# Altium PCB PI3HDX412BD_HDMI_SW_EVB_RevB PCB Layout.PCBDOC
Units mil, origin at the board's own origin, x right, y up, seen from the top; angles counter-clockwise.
Board outline 3710 x 2823 mil, 4 copper layers (Top Layer, MidLayer2, MidLayer1, Bottom Layer); 75 components, 78 nets, 342 pads, 126 vias.
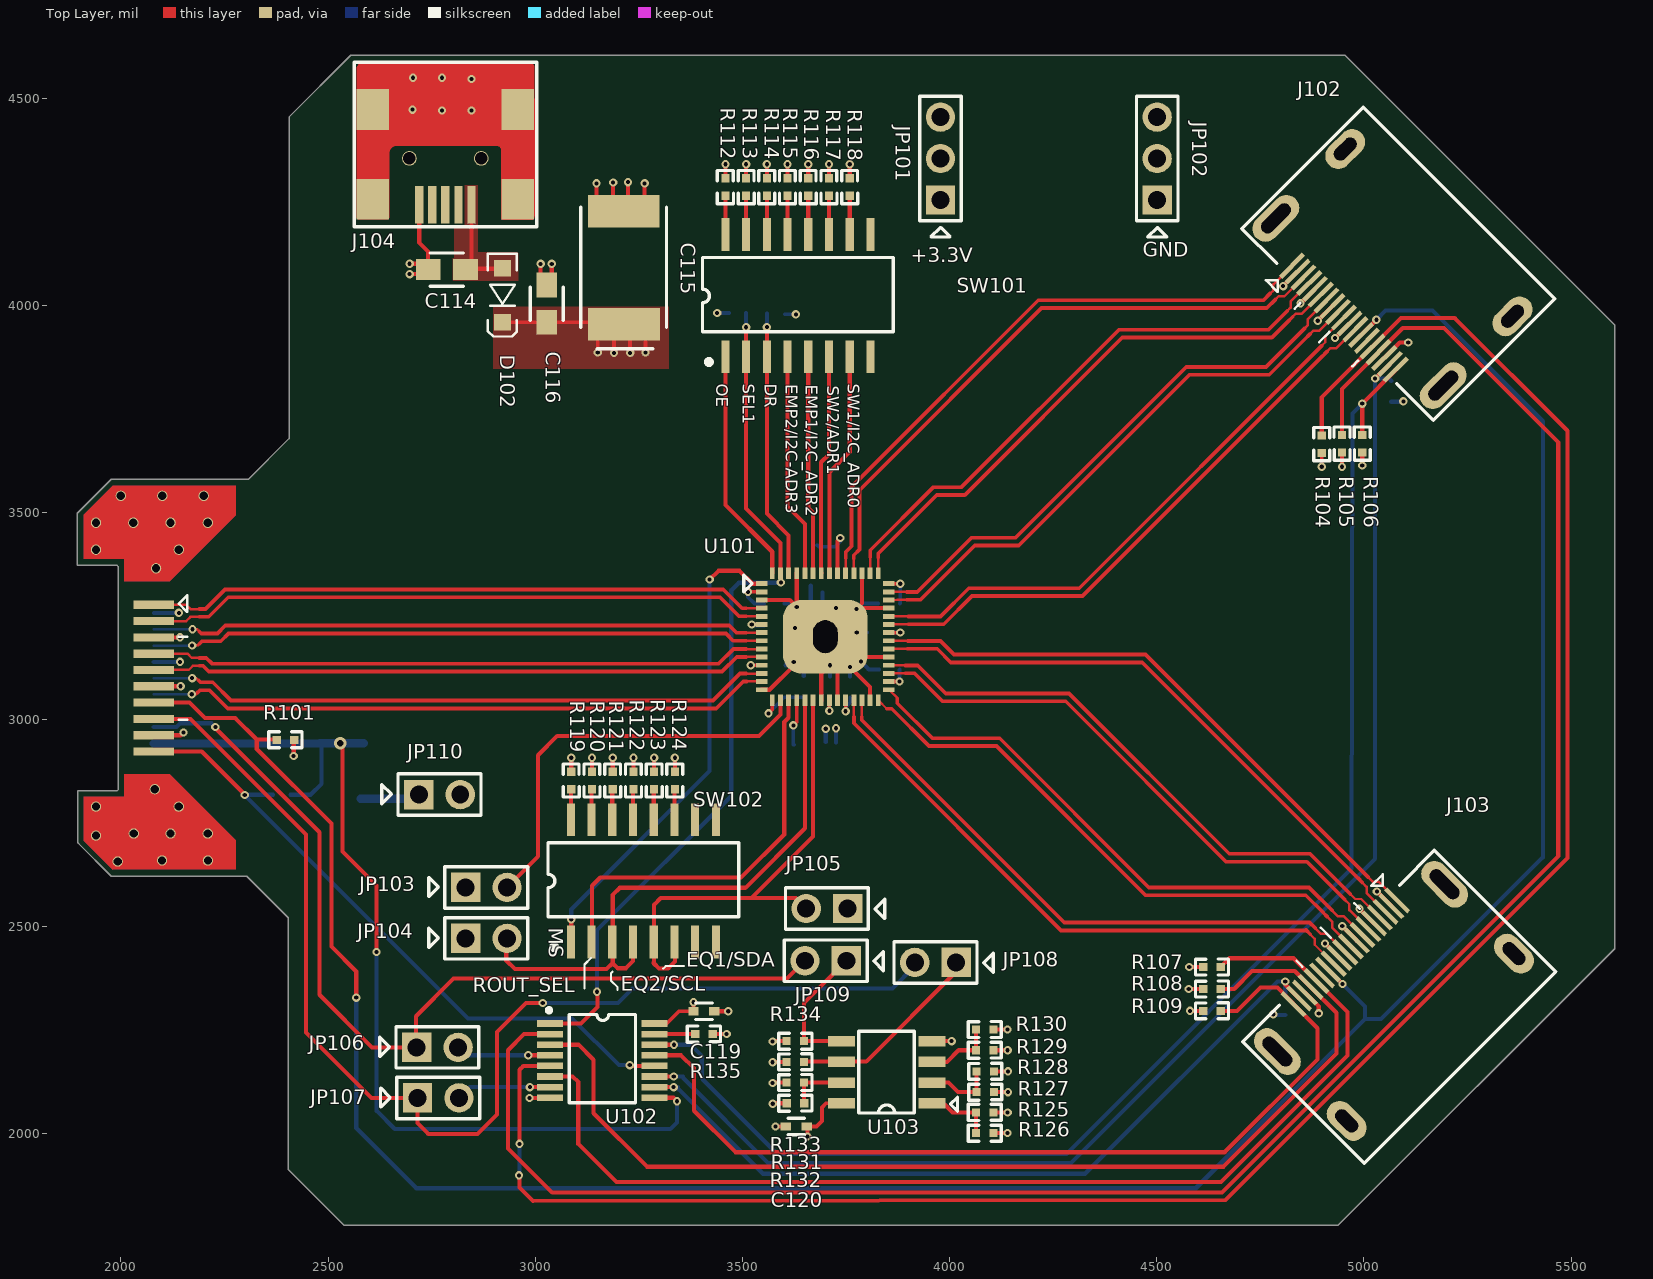
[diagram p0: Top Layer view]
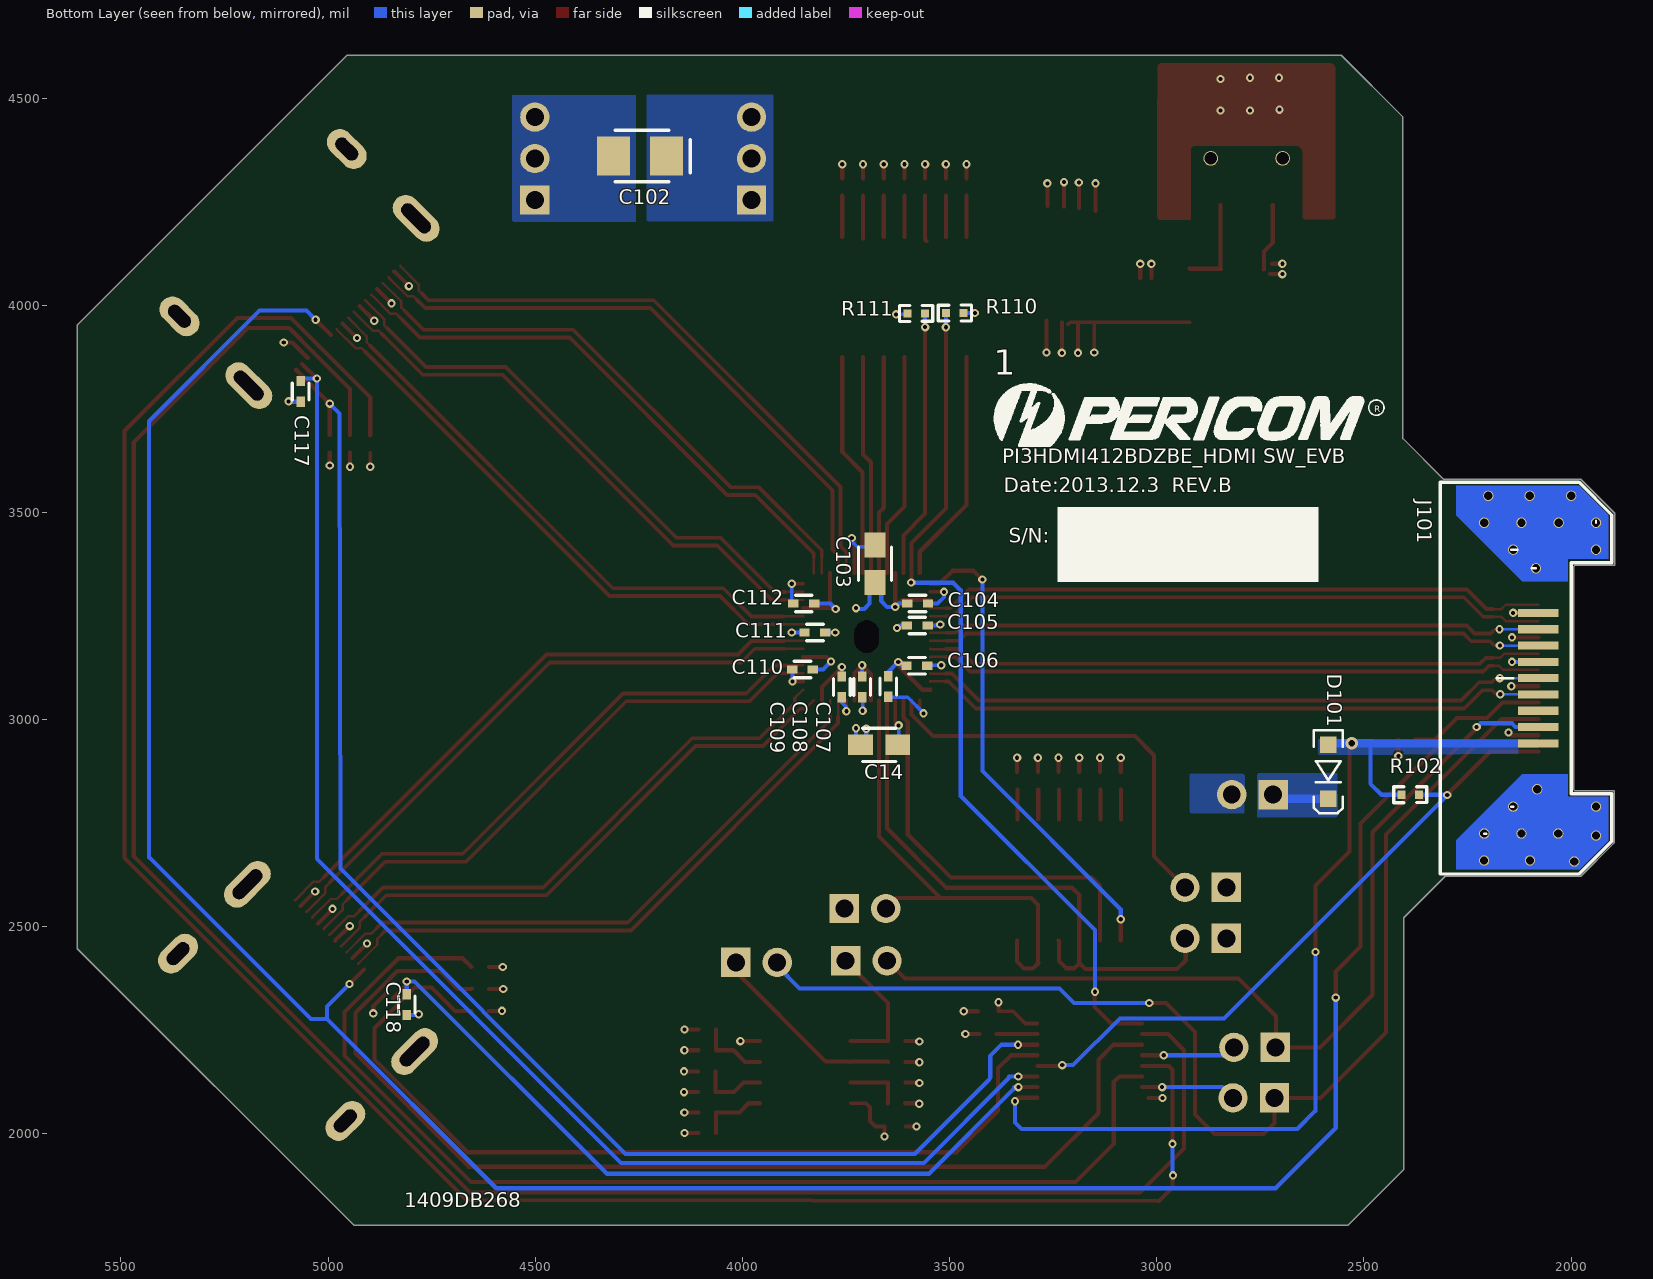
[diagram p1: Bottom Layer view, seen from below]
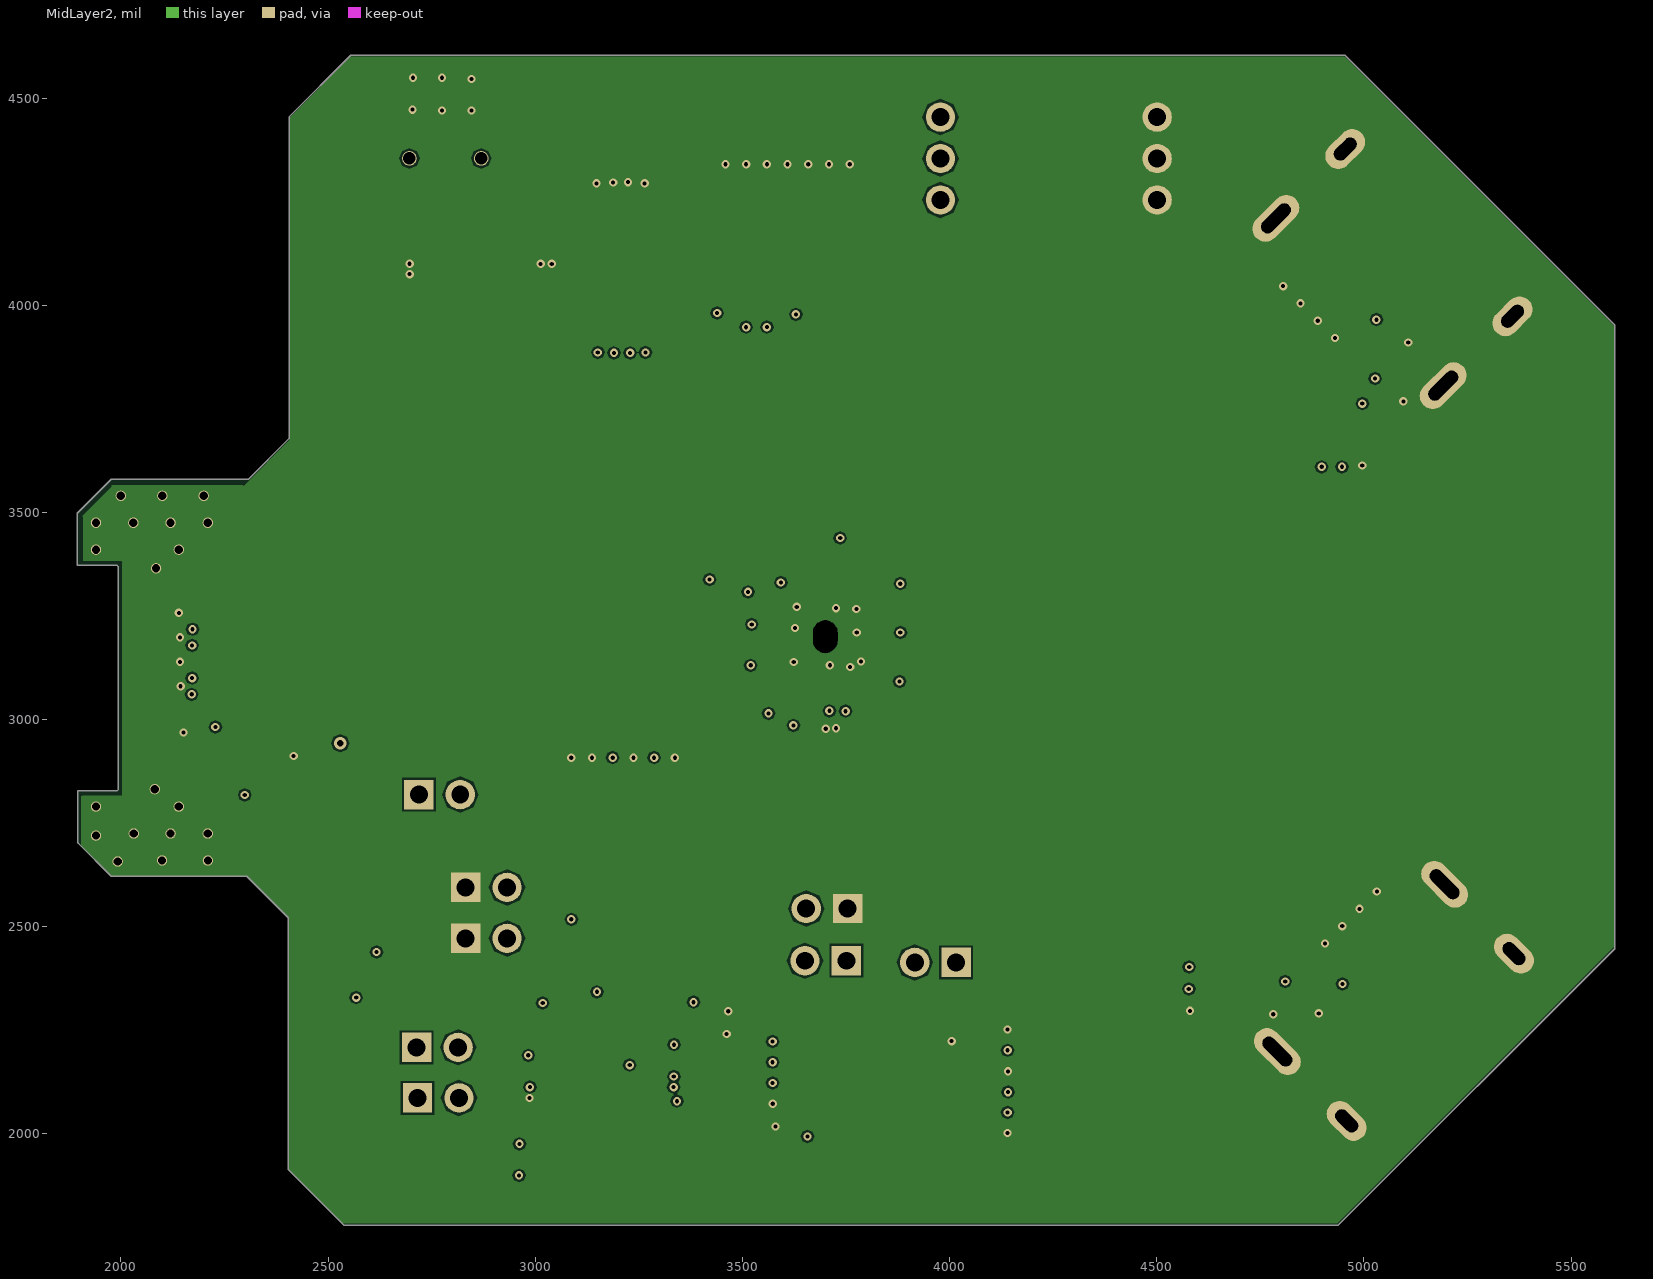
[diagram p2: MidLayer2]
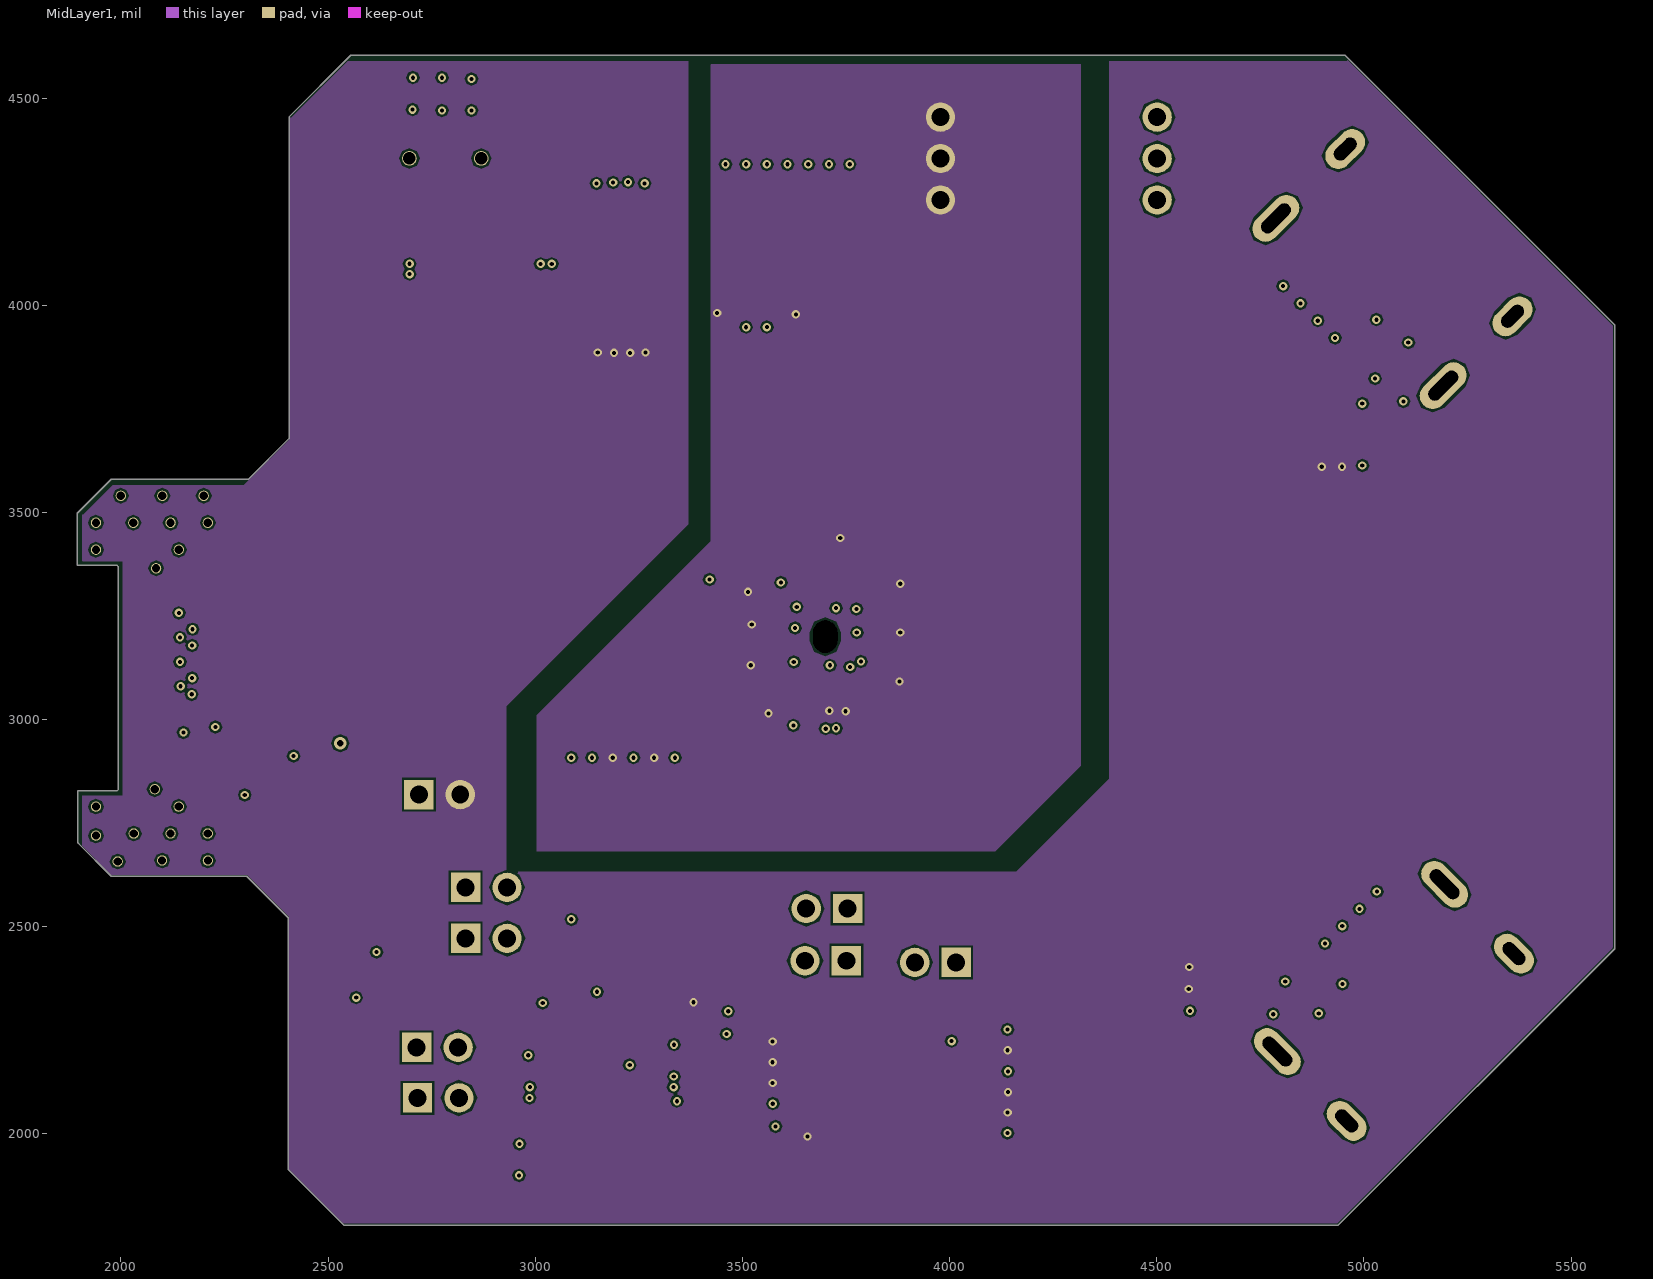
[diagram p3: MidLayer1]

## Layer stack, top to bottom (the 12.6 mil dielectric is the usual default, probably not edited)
Top Layer: signal copper 1.4
Dielectric: core 12.6, FR-4, Dk 4.8
MidLayer2: signal copper 1.4
Dielectric: prepreg 12.6, FR-4, Dk 4.8
MidLayer1: signal copper 1.4
Dielectric: core 12.6, FR-4, Dk 4.8
Bottom Layer: signal copper 1.4

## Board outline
1898,2701 1896,2703 1896,2828 1991,2828 1994,2831 1994,3369 1991,3372 1895,3372 1895,3498 1977,3580 2308,3580 2406,3678 2406,4454 2555,4603 4954,4603 5605,3952 5605,2447 4938,1780 2538,1780 2404,1914 2404,2522 2304,2622 1977,2622

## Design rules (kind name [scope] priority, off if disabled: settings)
Clearance [All] p1: gap=5
ComponentClearance [All] p1: gap=0 collisioncheckmode=3 verticalgap=0 showdistances=FALSE
DiffPairsRouting [All] p1: maxlimit=10 minlimit=10 mostfreqgap=10 maxuncoupledlength=500
FabricationTestPointUsage TestPointUsage [All] p1: valid=0 allowmultiple=FALSE
FabricationTestpoint Testpoint [All] p1: side=3 testpointundercomponent=TRUE minsize=40 maxsize=100 preferedsize=60 minholesize=0 maxholesize=40 preferedholesize=32 testpointgrid=1 allowsidetop=TRUE allowsidebottom=TRUE usegrid=TRUE gridtolerance=0.01
PlaneConnect [All] p1: planeconnectstyle=Direct reliefexpansion=20 reliefentries=4 reliefconductorwidth=10 reliefairgap=10
PolygonConnect [All] p1: connectstyle=Direct reliefconductorwidth=10 reliefentries=4 polygonreliefangle="90 Angle" airgapwidth=10
RoomDefinition PAGE1 [InComponentClass('PAGE1')] p1: confinementstyle=ConfineIn formatcopy=TRUE lockcomponents=FALSE outline 685,650 29830,650 29830,6385 685,6385
RoutingVias [All] p1: holewidth=10 width=20 viastyle="Through Hole" minholewidth=8 minwidth=10 maxholewidth=28 maxwidth=100
SolderMaskExpansion [All] p1: expansion=4
Width [All] p1: maxlimit=100 minlimit=5 preferedwidth=10 midlayer1_minwidth=10 midlayer1_maxwidth=10 midlayer2_minwidth=10 midlayer2_maxwidth=10 minimp=50.000000 maximp=50.000000 favimp=50.000000
23 further rules are at their usual default settings.

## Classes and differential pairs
differential pair NewDifferentialPair12: +D2-_2 -D2+_2
differential pair NewDifferentialPair11: +D2- -D2+
differential pair NewDifferentialPair10: +D2-_1 -D2+_1
differential pair NewDifferentialPair9: +D1-_2 -D1+_2
differential pair NewDifferentialPair8: +D1-_1 -D1+_1
differential pair NewDifferentialPair7: +D1- -D1+
differential pair NewDifferentialPair6: +D0-_2 -D0+_2
differential pair NewDifferentialPair5: +D0-_1 -D0+_1
differential pair NewDifferentialPair4: +D0- -D0+
differential pair NewDifferentialPair3: +CK-_2 -CK+_2
differential pair NewDifferentialPair2: +CK- -CK+
differential pair NewDifferentialPair1: +CK-_1 -CK+_1

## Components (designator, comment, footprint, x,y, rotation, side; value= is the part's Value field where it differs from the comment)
1 "" PSC_LOG 3284.3,3764.27 r180 bottom
C14 "1u_0805" CC_0805 3670,2939 r0 bottom
C102 "22u 3528" CAP@CT_3528 4247,4360 r0 bottom
C103 "10u_0805" CC_0805 3680,3376 r270 bottom
C104 "0.1u_0402" CC_0402 3577,3280 r0 bottom
C105 "0.1u_0402" CC_0402 3578,3227 r0 bottom
C106 "0.1u_0402" CC_0402 3579,3130 r0 bottom
C107 "0.1u_0402" CC_0402 3648,3080 r90 bottom
C108 "0.1u_0402" CC_0402 3711,3079 r90 bottom
C109 "0.1u_0402" CC_0402 3760,3079 r90 bottom
C110 "0.1u_0402" CC_0402 3855,3121 r180 bottom
C111 "0.1u_0402" CC_0402 3825,3210 r180 bottom
C112 "0.1u_0402" CC_0402 3852,3280 r180 bottom
C114 "4.7u" CAP@CC_0805 2787,4086 r180 top
C115 "100u" CAP@CT_7343 3214,4072 r270 top
C116 "1u" CAP@CC_0805 3028,4004 r90 top
C117 "0.1u_0402" CC_0402 5066,3792 r90 bottom
C118 "0.1u_0402" CC_0402 4810,2312 r90 bottom
C119 "0.1u_0402" CC_0402 3407,2296 r0 top
C120 "0.1u_0402" CC_0402 3630,2018 r180 top
D101 "B0520LW" D@SOD-123 2586,2874 r270 bottom
D102 "B0520LW" D@SOD-123 2921,4024 r270 top
J101 "CON_HDMI_Plug" CON_HDMI_Plug 2040,3100 r0 bottom
J102 "CON_HDMI_Recept" CON_HDMI_Recept 4834,4103 r135 top
J103 "CON_HDMI_Recept" CON_HDMI_Recept 5088,2556 r45 top
J104 "CON_USB2.0_MiniB_SMT" CON_USB2.0_MiniB_SMT 2783,4561 r270 top
JP101 "3x1 Pin Header" "3x1 Pin Header" 3978,4254 r90 top
JP102 "3x1 Pin Header" "3x1 Pin Header" 4501,4254 r90 top
JP103 "2x1 Pin Header" "2x1 Pin Header" 2832,2595 r0 top
JP104 "2x1 Pin Header" "2x1 Pin Header" 2832,2472 r0 top
JP105 "2x1 Pin Header" "2x1 Pin Header" 3754,2544 r180 top
JP106 "2x1 Pin Header" "2x1 Pin Header" 2714,2209 r0 top
JP107 "2x1 Pin Header" "2x1 Pin Header" 2716,2087 r0 top
JP108 "2x1 Pin Header" "2x1 Pin Header" 4016,2414 r180 top
JP109 "2x1 Pin Header" "2x1 Pin Header" 3751,2418 r180 top
JP110 "2x1 Pin Header" "2x1 Pin Header" 2719,2819 r0 top
R101 "100k_0402" R_0402 2397,2951 r0 top
R102 "1k_0402" R_0402 2388.35,2818.65 r180 bottom
R104 "2K2" RES@R_0402 4898,3665 r270 top
R105 "2K2" RES@R_0402 4947,3666 r270 top
R106 "10K" RES@R_0402 4996,3666 r270 top
R107 "2K2" RES@R_0402 4633.27,2402.97 r180 top
R108 "2K2" RES@R_0402 4633.27,2349.97 r180 top
R109 "10K" RES@R_0402 4633.27,2296.97 r180 top
R110 "10k_0402" R_0402 3487,3981 r0 bottom
R111 "10k_0402" R_0402 3581,3980 r180 bottom
R112 "4k7_0402" R_0402 3458.97,4285 r90 top
R113 "0_0402" R_0402 3508.97,4285 r90 top
R114 "0_0402" R_0402 3558.97,4285 r90 top
R115 "4k7_0402" R_0402 3608.97,4285 r90 top
R116 "4k7_0402" R_0402 3658.97,4285 r90 top
R117 "4k7_0402" R_0402 3708.97,4285 r90 top
R118 "4k7_0402" R_0402 3758.97,4285 r90 top
R119 "4k7_0402" R_0402 3087,2853 r90 top
R120 "4k7_0402" R_0402 3137,2853 r90 top
R121 "4k7_0402" R_0402 3187,2853 r90 top
R122 "4k7_0402" R_0402 3237,2853 r90 top
R123 "4k7_0402" R_0402 3287,2853 r90 top
R124 "4k7_0402" R_0402 3337,2853 r90 top
R125 "NP/47K" RES@R_0402 4085,2052 r0 top
R126 "47K" RES@R_0402 4085,2002 r180 top
R127 "NP/47K" RES@R_0402 4086,2101 r0 top
R128 "47K" RES@R_0402 4086,2151 r180 top
R129 "NP/47K" RES@R_0402 4085,2202 r0 top
R130 "47K" RES@R_0402 4085,2252 r180 top
R131 "NP/47K" RES@R_0402 3628,2124 r180 top
R132 "47K" RES@R_0402 3628,2074 r0 top
R133 "47K" RES@R_0402 3628,2174 r180 top
R134 "47K" RES@R_0402 3628,2224 r180 top
R135 "4k7_0402" R_0402 3407,2241 r0 top
SW101 "SW_X8_DIP" SW_X8_Half_Pitch 3634,4023 r0 top
SW102 "SW_X8_DIP" SW_X8_Half_Pitch 3261,2611 r0 top
U101 "PI3HDMI412BDZBE@TQFN56" TQFN56L8*8 3700,3200 r0 top
U102 "PI5C3257@TSSOP16" TSSOP16 3162,2177 r270 top
U103 "AT24C02B" SOIC8 3848,2149 r90 top

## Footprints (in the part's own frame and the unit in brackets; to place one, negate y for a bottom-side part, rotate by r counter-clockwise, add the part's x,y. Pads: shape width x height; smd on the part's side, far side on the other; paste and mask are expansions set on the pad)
"2x1 Pin Header" [mm] "Pin Header 2x1 Pitch 2.54mm"
  rect 1.8x1.8 hole 1.1: 1(0,0)
  round 1.8 hole 1.1: 2(2.54,0)
  silkscreen extent -2.27,-1.27 3.81,1.27
"3x1 Pin Header" [mm] "Pin Header 3x1 Pitch 2.54mm"
  rect 1.8x1.8 / inner round 1.8 / far side rect 1.8x1.8 hole 1.1: 1(0,0)
  round 1.8 hole 1.1: 2(2.54,0) 3(5.08,0)
  silkscreen extent -2.27,-1.27 6.35,1.27
CAP@CC_0805 [mil]
  rect 60x50 smd mask+4: 1(-45,0) 2(45,0)
  silkscreen extent -40,-40 40,40
CAP@CT_3528 [mil]
  rect 80x95 smd mask+4: 1(-64,0) 2(64,0)
  silkscreen extent -121,-62 60,62
CAP@CT_7343 [mm]
  rect 2x4.4 smd mask+0.102: 1(3,0) 2(-3.926,-0.011)
  silkscreen extent -4.19,-2.64 4.5,2.62
CC_0402 [mil]
  rect 25x20 smd: 1(-25,0) 2(25,0)
  silkscreen extent -20,-20 20,20
CC_0805 [mil]
  rect 60x50 smd: 1(-45,0) 2(45,0)
  silkscreen extent -40,-40 40,40
CON_HDMI_Plug [mm]
  rect 2.5x0.5 smd far side: 1(1,-4.5) 3(1,-3.5) 5(1,-2.5) 7(1,-1.5) 9(1,-0.5) 11(1,0.5) 13(1,1.5) 15(1,2.5) 17(1,3.5) 19(1,4.5)
  rect 2.5x0.5 smd: 2(1,-4) 4(1,-3) 6(1,-2) 8(1,-1) 10(1,0) 12(1,1) 14(1,2) 16(1,3) 18(1,4)
  round 0.635 hole 0.508: 20(-2.54,-9.525) 20(-2.54,-7.874) 20(-2.54,7.874) 20(-2.54,9.652) 20(-1.21,11.24) 20(-1.016,-11.176) 20(-0.254,-9.525) 20(-0.22,9.525) 20(1.067,6.807) 20(1.143,-6.731) 20(1.51,11.176) 20(1.524,-11.176) 20(2.032,-9.525) 20(2.032,9.525) 20(2.54,-7.874) 20(2.54,7.874) 20(4.064,-11.176) 20(4.318,-9.525) 20(4.318,9.525) 20(4.32,11.18)
  Top Layer region: -0.813,5.893 1.968,5.893 6.013,9.938 6.013,11.728 -1.517,11.728 -1.524,11.735 -3.302,9.957 -3.302,7.264 -0.813,7.264
  Top Layer region: -0.813,-5.944 1.968,-5.944 6.013,-9.989 6.013,-11.779 -1.517,-11.779 -1.524,-11.786 -3.302,-10.008 -3.302,-7.315 -0.813,-7.315
  Bottom Layer region: -0.813,5.893 1.968,5.893 6.013,9.938 6.013,11.728 -1.517,11.728 -1.524,11.735 -3.302,9.957 -3.302,7.264 -0.813,7.264
  Bottom Layer region: -0.813,-5.944 1.968,-5.944 6.013,-9.989 6.013,-11.779 -1.517,-11.779 -1.524,-11.786 -3.302,-10.008 -3.302,-7.315 -0.813,-7.315
  silkscreen extent -3.5,-12 7,12
CON_HDMI_Recept [mm]
  rect 0.28x2 smd: 1(0,0.281) 2(-0.5,0.281) 3(-1,0.281) 4(-1.5,0.281) 5(-2,0.281) 6(-2.5,0.281) 7(-3,0.281) 8(-3.5,0.281) 9(-4,0.281) 10(-4.5,0.281) 11(-5,0.281) 12(-5.5,0.281) 13(-6,0.281) 14(-6.5,0.281) 15(-7,0.281) 16(-7.5,0.281) 17(-8,0.281) 18(-8.5,0.281) 19(-9,0.281)
  oval 1.6x3.4 hole 0.8 slot 2.25 at 90 deg: 20(-11.75,-1.08) 21(2.75,-1.08)
  oval 1.6x2.8 hole 0.8 slot 1.65 at 90 deg: 22(-11.75,-7.09) 23(2.75,-7.09)
  silkscreen extent -12.82,-9.68 3.78,2.41
CON_USB2.0_MiniB_SMT [mm]
  rect 2.3x0.5 smd: 1(8.1,1.6) 2(8.1,0.8) 3(8.1,0) 4(8.1,-0.8) 5(8.1,-1.6)
  rect 2.5x2 smd: 5(2.25,4.45) 5(2.25,-4.45) 5(7.75,4.45) 5(7.75,-4.45)
  round 0.9 hole 0.762 unplated: 10(5.25,-2.2) 11(5.25,2.2)
  Top Layer region: 1.58,5.45 -0.35,5.45 -0.438,5.432 -0.513,5.383 -0.562,5.308 -0.58,5.22 -0.58,5.22 -0.58,-5.09 -0.553,-5.224 -0.477,-5.337 -0.364,-5.413 -0.23,-5.44 -0.23,-5.44 8.81,-5.44 8.875,-5.427 8.93,-5.39 8.967,-5.335 8.98,-5.27 8.98,-5.27 8.98,-3.59 8.968,-3.529 8.933,-3.477 8.881,-3.442 8.82,-3.43 8.82,-3.43 4.93,-3.43 4.758,-3.396 4.612,-3.298 4.514,-3.152 4.48,-2.98 4.48,-2.98 4.48,3.17 4.5,3.269 4.556,3.354 4.641,3.41 4.74,3.43 4.74,3.43 8.93,3.43 8.964,3.437 8.994,3.456 9.013,3.486 9.02,3.52 9.02,3.52 9.02,5.26 9.004,5.34 8.958,5.408 8.89,5.454 8.81,5.47 8.81,5.47 1.6,5.47 1.592,5.468 1.586,5.464 1.582,5.458 1.58,5.45
  silkscreen extent -0.65,-5.59 9.45,5.6
D@SOD-123 [mil]
  rect 40x40 smd mask+4: 1(-65,0) 2(65,0)
  silkscreen extent -100,-35 100,35
PSC_LOG [mil]
  silkscreen extent -107,-103 833,45
R_0402 [mm]
  rect 0.5x0.5 smd: 1(-0.532,-0.001) 2(0.54,-0.001)
  silkscreen extent -1.02,-0.49 1.02,0.49
RES@R_0402 [mm]
  rect 0.5x0.5 smd mask+0.102: 1(-0.532,-0.001) 2(0.54,-0.001)
  silkscreen extent -1.02,-0.49 1.02,0.49
SOIC8 [mm]
  rect 0.65x1.65 smd: 1(-1.905,-2.775) 2(-0.635,-2.775) 3(0.635,-2.775) 4(1.905,-2.775) 5(1.905,2.775) 6(0.635,2.775) 7(-0.635,2.775) 8(-1.905,2.775)
  silkscreen extent -2.5,-4.35 2.5,1.7
SW_X8_Half_Pitch [mm] "CHS-08TA"
  rect 0.5x2 smd: 1(-4.445,-3.75) 2(-4.445,3.75) 3(-3.175,-3.75) 4(-3.175,3.75) 5(-1.905,-3.75) 6(-1.905,3.75) 7(-0.635,-3.75) 8(-0.635,3.75) 9(0.635,-3.75) 10(0.635,3.75) 11(1.905,-3.75) 12(1.905,3.75) 13(3.175,-3.75) 14(3.175,3.75) 15(4.445,-3.75) 16(4.445,3.75)
  silkscreen extent -5.85,-4.22 5.85,2.34
TQFN56L8*8 [mm]
  rect 0.7x0.3 smd mask+0.102: 1(-3.9,3.25) 2(-3.9,2.75) 3(-3.9,2.25) 4(-3.9,1.75) 5(-3.9,1.25) 6(-3.9,0.75) 7(-3.9,0.25) 8(-3.9,-0.25) 9(-3.9,-0.75) 10(-3.9,-1.25) 11(-3.9,-1.75) 12(-3.9,-2.25) 13(-3.9,-2.75) 14(-3.9,-3.25) 29(3.9,-3.25) 30(3.9,-2.75) 31(3.9,-2.25) 32(3.9,-1.75) 33(3.9,-1.25) 34(3.9,-0.75) 35(3.9,-0.25) 36(3.9,0.25) 37(3.9,0.75) 38(3.9,1.25) 39(3.9,1.75) 40(3.9,2.25) 41(3.9,2.75) 42(3.9,3.25)
  rect 0.3x0.7 smd mask+0.102: 15(-3.25,-3.9) 16(-2.75,-3.9) 17(-2.25,-3.9) 18(-1.75,-3.9) 19(-1.25,-3.9) 20(-0.75,-3.9) 21(-0.25,-3.9) 22(0.25,-3.9) 23(0.75,-3.9) 24(1.25,-3.9) 25(1.75,-3.9) 26(2.25,-3.9) 27(2.75,-3.9) 28(3.25,-3.9) 43(3.25,3.9) 44(2.75,3.9) 45(2.25,3.9) 46(1.75,3.9) 47(1.25,3.9) 48(0.75,3.9) 49(0.25,3.9) 50(-0.25,3.9) 51(-0.75,3.9) 52(-1.25,3.9) 53(-1.75,3.9) 54(-2.25,3.9) 55(-2.75,3.9) 56(-3.25,3.9)
  rrect50% 5.2x4.5 smd mask+0.102: 57(0,0)
  oval 2x4 / inner round 0 / far side round 0 hole 1.5 slot 2 at 90 deg mask+0.102: 57(0,0)
  silkscreen extent -4.99,2.76 -4.49,3.76
TSSOP16 [mm] "CHS-08TA"
  rect 0.4x1.6 smd: 1(-2.275,-3.204) 2(-1.625,-3.204) 3(-0.975,-3.204) 4(-0.325,-3.204) 5(0.325,-3.204) 6(0.975,-3.204) 7(1.625,-3.204) 8(2.275,-3.204) 9(2.275,3.204) 10(1.625,3.204) 11(0.975,3.204) 12(0.325,3.204) 13(-0.325,3.204) 14(-0.975,3.204) 15(-1.625,3.204) 16(-2.275,3.204)
  silkscreen extent -3.21,-3.4 2.58,2.04

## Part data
C14: library part C_1.0u_0805
C102: library part "22UF 3528"
C103: library part C_10u_0805
C104 C105 C106 C107 C108 C109 C110 C111 C112 C117 C118 C119 C120: library part C_0.1u_0402
C114 C116: library part "CHIP CAP0805"
C115: library part "100UF 7343_1"
D101 D102: library part SchottkyDiode@SOD-123_1
JP103 JP104 JP105 JP106 JP107: library part "2x1 Pin Header_Dup1"
R101 R102 R110 R111 R112 R113 R114 R115 R116 R117 R118 R119 R120 R121 R122 R123 R124 R135: library part R_0402
R104 R105 R106 R107 R108 R109 R125 R126 R127 R128 R129 R130 R131 R132 R133 R134: library part "CHIP RES0402_0"
U101: library part PI3HDMI412AD@TQFN56_4
U102: library part PI5C3244@TSSOP20_1
U103: library part 24C02@SOIC8

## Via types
v1: diameter 20, hole 10, Top Layer to Bottom Layer, tented both sides, 125 vias
v2: diameter 30, hole 15, Top Layer to Bottom Layer, tented both sides, 1 vias

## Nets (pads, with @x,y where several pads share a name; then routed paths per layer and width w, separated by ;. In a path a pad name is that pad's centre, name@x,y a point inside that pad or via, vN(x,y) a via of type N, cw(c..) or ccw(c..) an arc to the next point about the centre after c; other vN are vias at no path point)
+3V3: C102.1 C103.1 C104.1 C105.1 C106.1 C107.1 C108.1 C109.1 C110.1 C111.1 C112.1 JP101.1 JP101.2 JP101.3 R110.1 R111.1 R121.2 R123.2 U101.2 U101.6 U101.11 U101.15 U101.22 U101.24 U101.30 U101.36 U101.42 U101.48 | length 928.1
  Top Layer w9: v1(3513.73,3308.27) U101.2 ; v1(3520,3131) 3520.1,3131.1 U101.11 ; v1@3522,3229 v1(3522.53,3229.53) U101.6 ; v1(3563,3015) 3572.05,3024.05 U101.15 ; v1(3709.84,3021.16) U101.22 ; U101.48 3729.53,3431.53 v1(3736,3438) ; v1(3749.21,3020.21) U101.24 ; U101.30 3878.73,3091.73 v1@3879,3092 ; U101.36 3880.84,3209.84 v1(3881,3210) ; U101.42 v1(3880.95,3327.95) v1(3880.95,3327.95)
  Top Layer w10: R121.2 v1(3187.03,2908.03) ; R123.2 v1(3287.03,2908.03)
  Bottom Layer w9: v1(3513.73,3308.27) 3513,3307.54 3513,3296 3529,3280 C104.1 ; v1(3520,3131) C106.1@3543,3131 ; v1(3522.53,3229.53) 3525.06,3227 C105.1 ; v1(3563,3015) 3563,3016 3601,3054 3647,3054 C107.1 ; R111.1@3601.95,3977.97 v1(3629,3977.97) ; C103.1 3684,3417 3723,3417 3736,3430 v1(3736,3438) ; v1(3709.84,3021.16) 3709.84,3052.84 C108.1 ; v1(3749.21,3020.21) 3749.21,3030.21 3760,3041 C109.1 ; C111.1 v1(3881,3210) ; v1(3879.36,3092) 3879.36,3120.36 C110.1 ; C112.1@3880,3280 3880.95,3280.95 v1(3880.95,3327.95)
  Bottom Layer w10: v1(3438.97,3981.03) R110.1@3468.05,3981.03
+5V: C115.1 C116.1 C119.1 C120.1 D102.2 JP110.2 R104.2 R105.2 R107.2 R108.2 R125.2 R127.2 R129.2 R131.2 R133.2 R134.2 U102.16 U103.8 | length 1209
  Top Layer w9: D102.2 3208.89,3959 C115.1 ; v1(3151,3886) C115.1@3151,3959 ; v1(3190,3885) C115.1@3190,3959 ; v1(3229,3885) C115.1@3229,3958 ; v1(3266,3886) C115.1@3266,3964 ; U102.16 3317.57,2266.57 3347,2296 C119.1 v1(3382,2318) ; v1(3657,1994) 3657,2018 3679,2018 3692,2031 3692,2064 3702,2074 U103.8 ; v1(4577.27,2350) R108.2 ; v1(4578.3,2403) R107.2 ; v1(4897.97,3610.03) R104.2 ; v1(4947,3610) R105.2
  Top Layer w10: v1@3572.97,2124.03 R131.2 ; v1@3572.97,2174.03 R133.2 ; v1@3572.97,2224.03 R134.2 ; R125.2 v1(4140.03,2051.97) ; R129.2 v1(4140.03,2201.97) ; R127.2 v1(4141.03,2100.97)
  other v1: 3572.97,2123.03 3572.97,2173.03 3572.97,2223.03
+5V_1: C117.2 J102.18 U102.11 | length 3377.1
  Top Layer w10: U102.11 v1(3334.39,2138.61) v1@3335,2138 ; v1(5027,3823) 5062.55,3858.55 J102.18
  Bottom Layer w10: v1(3334.39,2138.61) 3356.39,2138.61 ; 3358.39,2133.61 3562,1930 4293,1930 5027,2664 v1(5027,3823) 5060,3823 C117.2
+5V_2: C118.2 J103.18 U102.10 | length 1882.3
  Top Layer w10: U102.10 v1(3334,2113) ; v1(4810,2368) 4810,2361 4843.55,2327.45 J103.18
  Bottom Layer w10: v1(3334,2113) v1@3343.98,2113.02 ; 3345.98,2108.02 3550,1904 4327,1904 4791,2368 v1(4810,2368) C118.2
+5V_S: D101.1 J101.18 R102.1 U102.9 | length 2472.6
  Top Layer w10: v2(2529.33,2942.85) 2535,2937.18 2535,2682 2617,2600 v1(2617,2439) ; U102.9 3333.57,2087.43 v1(3342,2079)
  Bottom Layer w10: R102.1 2457.62,2818.62 2484,2845 2484,2938.74 2480.02,2942.72 ; 2617,2055 v1(2617,2439) ; 2618,2055 2661,2012 3326,2012 3342,2028 v1(3342,2079)
  Bottom Layer w19.68: J101.18 2463.69,2942.52 ; 2463.69,2942.68 2480.02,2942.72 v2(2529.33,2942.85) D101.1@2586,2943
+5V_USB: C114.1 D102.1 J104.1 | length 230.9
  Top Layer w10: C114.1@2845,4087 C114.1@2845.99,4087.99 ; J104.1 C114.1@2845.99,4087.99 ; D102.1 2919.99,4087.99 C114.1@2845.99,4087.99
A0: R125.1 R126.2 U103.1 | length 166
  Top Layer w10: U103.1 3985,2074 4007,2052 R125.1 4064.02,2002.31 R126.2
A1: R127.1 R128.2 U103.2 | length 167.5
  Top Layer w10: U103.2 3997,2124 4020,2101 R127.1 ; R128.2 4064.73,2101.28 R127.1
A2: R129.1 R130.2 U103.3 | length 168.6
  Top Layer w10: U103.3 3994,2174 4022,2202 R129.1 4064.02,2251.75 R130.2
CEC: J101.13 J102.13 J103.13 R101.1 | length 6407.8
  Top Layer w10: J101.13 2166.06,3040.94 2203,3004 2275.97,3004 2328,2951.97 ; R101.1@2376.05,2951.97 2328,2951.97 ; v1(2568,2329) 2568,2392 2508,2452 2508,2749 2328,2929 2328,2951.97 ; J103.13 4913.21,2396.79 v1(4948,2362) ; J102.13 4993.21,3928.21 v1(5030,3965)
  Bottom Layer w10: v1(2568,2329) 2568,2014 2713,1869 4594,1869 5002.27,2277.27 ; v1(4948,2362) 5002.27,2307.73 5002.27,2277.27 ; v1(5030,3965) 5052,3987 5165,3987 5432,3720 5432,2667 ; 5431,2667 5041.27,2277.27 5002.27,2277.27
CK+: J101.10 U101.12 | length 1516.6
  Top Layer w6: v1(2172,3100) 2182,3100 2186.79,3095.21 ; 3509,3111.07 3546.11,3111.07 U101.12
  Top Layer w9: 2186.79,3095.21 2192,3090 2221.87,3090 2265.87,3046 3429.13,3046 3494.2,3111.07 3509,3111.07
  Bottom Layer w6: J101.10 v1(2172,3100)
CK+_1: J102.10 U101.38 | length 1405.1
  Top Layer w6: U101.38 3873,3249.21 3873.34,3248.87 3901,3248.87 ; 4897.67,3901.71 4906.52,3910.56 4906.52,3924.97 J102.10
  Top Layer w9: 3901,3248.87 3977.87,3248.87 4046,3317 4312.95,3317 4897.67,3901.71
CK+_2: J103.10 U101.26 | length 1446.5
  Top Layer w6: 3788.24,3006 3788.24,3026.66 3788.58,3027 U101.26 ; 4882.25,2496.8 4895.56,2483.48 4909.97,2483.48 J103.10
  Top Layer w9: 3788.24,3006 3788.24,2998.76 4276.82,2510.18 4868.87,2510.18 4882.25,2496.8
CK-: J101.12 U101.13 | length 1516.7
  Top Layer w6: v1(2171,3061) 2181,3061 2185.21,3065.21 ; 3510,3092.07 3546.11,3092.07 U101.13
  Top Layer w9: 2185.21,3065.21 2191,3071 2214,3071 2258,3027 3437,3027 3502.07,3092.07 3510,3092.07
  Bottom Layer w6: J101.12 2079.74,3061 v1(2171,3061)
CK-_1: J102.12 U101.37 | length 1422.2
  Top Layer w6: U101.37 3853.89,3229.87 3900,3229.87 ; 4911.1,3888.28 4919.11,3896.29 4933.52,3896.29 J102.12
  Top Layer w9: 3900,3229.87 3985.74,3229.87 4053.87,3298 4320.82,3298 4898.82,3876 ; 4897.92,3875.1 4911.1,3888.28
CK-_2: J103.12 U101.25 | length 1463.6
  Top Layer w6: U101.25 3768.9,3027 3769.24,3026.66 3769.24,3006 ; 4870.26,2481.91 4881.29,2470.89 4881.29,2456.48 J103.12
  Top Layer w9: 3769.24,3006 3769.24,2990.89 4268.95,2491.18 4861,2491.18 ; 4860.1,2492.08 4870.26,2481.91
D0+: J101.7 U101.9 | length 1501.7
  Top Layer w6: J101.7 2160.94,3159.06 2171.13,3148.87 2189,3148.87 ; 3509.23,3170.13 3546.11,3170.13 U101.9
  Top Layer w9: 2189,3148.87 2206,3148.87 2219.87,3135 3335,3135 ; 3325,3135 3443.13,3135 3478.26,3170.13 3509.23,3170.13
D0+_1: J102.7 U101.41 | length 1356.2
  Top Layer w6: U101.41 3873,3308.27 3873.34,3307.93 3897,3307.93 ; 4856.27,3943.83 4864.76,3952.32 4864.76,3966.73 J102.7
  Top Layer w9: 3897,3307.93 3921.93,3307.93 4053,3439 4159,3439 4571,3851 4763.44,3851 4856.27,3943.83
D0+_2: J103.7 U101.29 | length 1395.3
  Top Layer w6: U101.29 3873.89,3051.7 ; 4922.92,2539.65 4937.32,2525.24 4951.73,2525.24 J103.7
  Top Layer w9: 3873.89,3051.7 3873.89,3039.54 3958.44,2955 4120.86,2955 4480.87,2595 4867.56,2595 4922.92,2539.65
D0-: J101.9 U101.10 | length 1491.7
  Top Layer w6: J101.9 2163.82,3119.68 2174,3129.87 2189,3129.87 ; 3509.23,3151.13 3546.11,3151.13 U101.10
  Top Layer w9: 2189,3129.87 2198.13,3129.87 2212,3116 3451,3116 3486.13,3151.13 3509.23,3151.13
D0-_1: J102.9 U101.40 | length 1373.2
  Top Layer w6: U101.40 3873,3288.58 3873.34,3288.93 3897,3288.93 ; 4870.07,3930.76 4877.35,3938.05 4891.76,3938.05 J102.9
  Top Layer w9: 3897,3288.93 3929.8,3288.93 4060.87,3420 4166.87,3420 4578.87,3832 4771.31,3832 4857.06,3917.76 ; 4856.16,3916.85 4870.07,3930.76
D0-_2: J103.9 U101.28 | length 1396.6
  Top Layer w6: U101.28 3848.3,3026.11 ; 4910.93,2524.76 4923.05,2512.65 4923.05,2498.24 J103.9
  Top Layer w9: 3848.3,3026.11 3860.46,3026.11 3950.57,2936 4112.99,2936 4473.01,2576 4859.69,2576 4902.76,2532.94 ; 4901.85,2533.84 4910.93,2524.76
D1+: J101.4 U101.7 | length 1486.5
  Top Layer w6: v1(2173,3218) 2184,3218 2189.37,3212.63 ; 3509.59,3209.5 3546.11,3209.5 U101.7
  Top Layer w9: 2189.37,3212.63 2194,3208 2202,3208 2233.13,3208 2252.13,3227 3468,3227 3485.5,3209.5 3509.59,3209.5
  Bottom Layer w6: J101.4 v1@2173,3218.11
D1+_1: J102.4 U101.44 | length 1390
  Top Layer w6: U101.44 3808.61,3353.89 3808.61,3392 ; 4814.88,3985.96 4823,3994.08 4823,4008.48 J102.4
  Top Layer w9: 3808.61,3392 3808.61,3408.48 3961.13,3561 4029,3561 4409,3941 4769.92,3941 4814.88,3985.96
D1+_2: J103.4 U101.32 | length 1435.9
  Top Layer w6: U101.32 3873,3131.1 3873.34,3130.76 3893,3130.76 ; 4966.85,2579.23 4979.08,2567 4993.48,2567 J103.4
  Top Layer w9: 3893,3130.76 3923.11,3130.76 3990.87,3063 4288,3063 4675,2676 4870.08,2676 4957.05,2589.03 ; 4957.95,2588.13 4966.85,2579.23
D1-: J101.6 U101.8 | length 1487.5
  Top Layer w6: v1(2172,3179) 2186,3179 2190,3183 2191,3183 ; 3509.23,3190.5 3546.11,3190.5 U101.8
  Top Layer w9: 2190,3183 2196,3189 2241,3189 2260,3208 3460.13,3208 3477.63,3190.5 3509.23,3190.5
  Bottom Layer w6: J101.6 v1@2172,3178.74
D1-_1: J102.6 U101.43 | length 1375.5
  Top Layer w6: 3827.61,3391 3827.61,3373.34 3827.95,3373 U101.43 ; 4827.95,3972.16 4835.6,3979.81 4850,3979.81 J102.6
  Top Layer w9: 3827.61,3391 3827.61,3400.61 3969,3542 4036.87,3542 4416.87,3922 4777.79,3922 4815.31,3959.52 ; 4814.4,3958.61 4827.95,3972.16
D1-_2: J103.6 U101.31 | length 1421.4
  Top Layer w6: U101.31 3873,3111.42 3873.34,3111.76 3893,3111.76 ; 4953.42,2565.79 4964.81,2554.4 4964.81,2540 J103.6
  Top Layer w9: 3893,3111.76 3915.24,3111.76 3983,3044 4280.13,3044 4667.13,2657 4862.21,2657 4953.42,2565.79
D2+: J101.1 U101.4 | length 1510.2
  Top Layer w6: J101.1 2157.83,3277.17 2169,3266 2190,3266 ; 3509,3268.56 3546.11,3268.56 U101.4
  Top Layer w9: 2190,3266.98 2204.11,3266.98 2251.13,3314 3405,3314 3453.87,3314 3499.32,3268.56 3509,3268.56
D2+_1: J102.1 U101.47 | length 1506
  Top Layer w6: U101.47 3749.21,3382.32 3749.56,3382.67 3749.56,3390 ; 4773.48,4028.08 4781.24,4035.84 4781.24,4050.24 J102.1
  Top Layer w9: 3749.56,3390 3749.56,3404.43 3763.38,3418.24 3763.38,3561.38 4214,4012 4757.4,4012 4773.48,4028.08
D2+_2: J103.1 U101.35 | length 1486.1
  Top Layer w6: U101.35 3882.32,3190.16 3882.67,3189.81 3899,3189.81 ; 5009.7,2619.9 5020.84,2608.76 5035.24,2608.76 J103.1
  Top Layer w9: 3899,3189.81 3978.06,3189.81 4010.87,3157 4472.6,3157 5009.7,2619.9
D2-: J101.3 U101.5 | length 1509.7
  Top Layer w6: J101.3 2157.8,3237.8 2167.98,3247.98 2190,3247.98 ; 3509,3249.56 3546.11,3249.56 U101.5
  Top Layer w9: 2190,3247.98 2211.98,3247.98 2259,3295 3405,3295 3446,3295 3491.44,3249.56 3509,3249.56
D2-_1: J102.3 U101.46 | length 1490.3
  Top Layer w6: 3768.56,3389 3768.56,3353.89 U101.46 ; 4786.19,4013.92 4793.84,4021.56 4808.24,4021.56 J102.3
  Top Layer w9: 3768.56,3389 3768.56,3396.56 3782.38,3410.38 3782.38,3553.51 4221.87,3993 4765.27,3993 4786.19,4013.92
D2-_2: J103.3 U101.34 | length 1471.6
  Top Layer w6: U101.34 3882.32,3170.47 3882.67,3170.81 3898,3170.81 ; 4995.9,2606.82 5006.56,2596.16 5006.56,2581.76 J103.3
  Top Layer w9: 3898,3170.81 3970.19,3170.81 4003,3138 4464.73,3138 4986.27,2616.45 ; 4985.37,2617.36 4995.9,2606.82
DR: R111.2 SW101.5 U101.54 | length 648.2
  Top Layer w10: v1(3558.94,3947) 3558.94,3497.06 3611.42,3444.58 U101.54
  Bottom Layer w10: v1(3558.94,3947) R111.2@3558.94,3979.97
EMP1/I2C_ADR2: SW101.9 U101.51 | length 525.9
  Top Layer w10: SW101.9@3658.94,3874.68 3658.94,3511.06 3670,3500 3670,3354.02 U101.51
EMP2/I2C_ADR3: SW101.7 U101.52 | length 538.7
  Top Layer w10: SW101.7@3608.94,3874.68 3608.94,3514.06 3651,3472 3651,3353.76 U101.52
EQ1/SDA_CTL: JP105.2 SW102.9 SW102.11 U101.20 | length 1179.1
  Top Layer w10: SW102.11@3337,2466.75 3337,2416 3323,2402 3323,2401 3321,2399 3299,2399 3286,2412 3286,2414 3287,2415 3287,2553 3303,2569 3629,2569 JP105.2 ; 3522,2569 3670.47,2717.47 U101.20
EQ2/SCL_CTL: JP104.2 SW102.5 SW102.7 U101.19 | length 1440.6
  Top Layer w10: JP104.2 2930,2470 2930,2419 2951,2398 3172,2398 3186,2412 3187,2412 ; SW102.7@3237,2466.75 3236,2465.75 3236,2417 3219,2400 3199,2400 3187,2412 ; U101.19 3650.79,2737.79 3507,2594 3204,2594 3187,2577 3187,2412
GND: C14.2 C102.2 C103.2 C104.2 C105.2 C106.2 C107.2 C108.2 C109.2 C110.2 C111.2 C112.2 C114.2 C115.2 C116.2 C117.1 C118.1 C119.2 C120.2 J101.2 J101.5 J101.8 J101.11 J101.17 J101.20 J102.2 J102.5 J102.8 J102.11 J102.17 J102.20 J102.21 J102.22 J102.23 J103.2 J103.5 J103.8 J103.11 J103.17 J103.20 J103.21 J103.22 J103.23 J104.5 JP102.1 JP102.2 JP102.3 JP103.1 JP104.1 JP105.1 R101.2 R106.2 R109.2 R112.2 R113.2 R114.2 R115.2 R116.2 R117.2 R118.2 R119.2 R120.2 R122.2 R124.2 R126.1 R128.1 R130.1 R132.1 R135.2 U101.3 U101.14 U101.21 U101.23 U101.27 U101.33 U101.39 U101.45 U101.53 U101.57 U102.8 U103.4 | length 3554.7
  Top Layer w10: J101.17 2144.2,2962.2 v1@2149,2967 ; J101.11 v1@2142.32,3080.32 ; J101.5 v1(2142.57,3198.43) v1@2143,3198 ; v1(2417,2912) 2417.27,2912.27 R101.2@2417.27,2950.97 ; v1(2697,4075) C114.2@2726,4075 ; v1(2697,4100) C114.2@2722,4100 ; J104.5@2720.01,4242.1 2720.01,4150.99 2741,4130 2741,4087 C114.2 ; v1(2986.24,2087) U102.8@3020,2087 ; C116.2@3013,4066 v1(3013,4099.76) ; C116.2@3040,4066 v1(3040,4099.76) ; R119.2 v1(3087.03,2908.03) ; R120.2 v1(3137.03,2908.03) ; C115.2@3148,4228 v1(3148,4294) ; C115.2@3188,4235 v1(3188,4296) ; C115.2@3224,4238 v1(3224,4297) ; R122.2 v1(3237.03,2908.03) ; C115.2@3264,4240 v1(3264,4294) ; R124.2 v1(3337.03,2908.03) ; R135.2 v1(3462.03,2240.97) ; C119.2 v1(3465.76,2296) ; R112.2 v1(3459,4340.03) ; R113.2 v1(3509,4340.03) ; U101.14 3565.05,3072.05 3624,3131 v1(3624,3139) ; U101.3 3614.42,3288.58 v1(3631,3272) 3631.1,3272.1 U101.53 ; R114.2 v1(3559,4340.03) ; v1@3573.28,2073.97 R132.1 ; v1(3580,2018) C120.2 ; R115.2 v1(3609,4340.03) ; R116.2 v1(3659,4340.03) ; U101.21 3690.16,3110.16 v1(3711,3131) 3729.53,3112.47 U101.23 ; R117.2 v1(3709,4340.03) ; R118.2 v1(3759,4340.03) ; v1(3760,3127) 3808.27,3078.73 U101.27 ; v1(3775,3267) 3788.58,3280.58 U101.45 ; U101.57@3779.92,3271.92 3782.94,3268.9 U101.39 ; v1(3786,3140) 3796.79,3150.79 U101.33 ; U103.4 v1(4005,2224) ; R126.1 v1(4139.72,2002.03) ; R130.1 v1(4139.72,2252.03) ; R128.1 v1(4140.72,2151.03) ; v1(4580.3,2297) R109.2 ; v1(4805,4046) 4840.1,4081.1 J102.2 ; v1(4846.76,4004.4) J102.5 ; J103.17 4857.89,2341.11 4891,2308 v1(4891,2291) ; v1(4888.52,3962.64) J102.8 ; v1(4905.89,2459.73) J103.11 ; v1(4930.27,3920.89) J102.11 ; v1(4947.64,2501.48) J103.8 ; v1(4989.4,2543.24) J103.5 ; v1(4995.97,3613.03) R106.2 ; v1(5031.16,2585) J103.2 ; J102.17 5086.42,3910 v1(5107,3910)
  Bottom Layer w9: J101.2 v1(2140,3257.48)
  Bottom Layer w10: J101.8 v1(2142.63,3139.37) v1@2143,3139 ; C104.2 3623,3280 v1(3631,3272) 3651,3272 3665,3286 C103.2@3665,3323 ; C105.2 3621,3227 v1(3627,3221) ; C106.2@3604,3131 3616,3131 v1(3624,3139) 3648,3115 C107.2 ; C103.2@3693,3307 3693,3280 3706,3267 3724,3267 v1(3726,3269) ; C14.2@3701,2946 v1(3701,2978) ; C108.2 v1(3711,3131) ; C14.2@3726,2945 v1(3726,2979) ; C109.2 v1(3760,3127) ; v1@3775,3209 v1(3776,3210) C111.2 ; v1(3775,3267) 3788,3280 C112.2 ; v1(3786,3140) 3805,3121 C110.2 ; v1(4781,2289) 4783,2287 C118.1 ; C117.1 5094,3767 v1(5095,3768)
  other v1: 3573.28,2072.97 2151,2969 2144.32,3080.32 2775,4470 2846,4470 2704,4472 2846,4546 2705,4549 2775,4549
HPD: J101.19 R102.2 U102.12 | length 1587.7
  Top Layer w10: J101.19 2195.17,2922.83 v1@2299.5,2818.5 ; v1@3229.8,2164.2 U102.12
  Bottom Layer w10: v1(2299,2818) 2299.62,2818.62 R102.2 ; v1@2300,2817 2838,2279 3089,2279 3202,2166 v1(3228,2166)
HPD_1: J102.19 R106.1 U102.14 | length 3425.5
  Top Layer w10: U102.14 v1(3335,2215.39) ; R106.1 R106.1 v1(4995.97,3762.51) 5076.73,3843.27 J102.19
  Bottom Layer w10: v1(3335,2215.39) 3374.61,2215.39 3402,2188 3402,2137 ; 3404,2132 3584,1952 4282,1952 4970.2,2640.2 4972,3738.62 v1(4995.97,3762.51)
HPD_2: J103.19 R109.1 U102.13 | length 2221.1
  Top Layer w10: U102.13 3352.2,2189.8 3383,2159 3383,2056 3483,1956 4664,1956 4888,2180 4888,2255 J103.19@4831,2312 ; R109.1 4694,2297 4750,2353 4791,2353 4829.63,2314.37 J103.19
MS: SW102.1 U101.1 | length 1156.6
  Top Layer w10: SW102.1@3087,2466.75 v1(3087,2518) ; v1(3421,3338) 3442,3359 3493,3359 3524.05,3327.95 U101.1
  Bottom Layer w10: v1(3087,2518) 3087,2542 3421,2876 v1(3421,3338)
NetC14_1: C14.1 U101.18 | length 113.6
  Top Layer w9: v1(3623,2986) 3631.1,2994.1 U101.18
  Bottom Layer w9: C14.1@3623,2939 v1(3623,2986) ; C14.1@3623,2941 C14.1
NetC114_2: 
NetD101_CATHODE: D101.2 JP110.1 | length 154
  Bottom Layer w19.68: D101.2@2578,2809 JP110.1@2732,2809
NetR112_1: R112.1 SW101.2 | length 99.7
  Top Layer w10: SW101.2@3458.9,4164.41 3458.9,4263.95 R112.1
NetR113_1: R113.1 SW101.4 | length 99.7
  Top Layer w10: SW101.4@3508.9,4164.41 3509,4164.5 R113.1
NetR114_1: R114.1 SW101.6 | length 110.3
  Top Layer w10: SW101.6@3555.97,4155 3559,4158.03 R114.1
NetR115_1: R115.1 SW101.8 | length 99.7
  Top Layer w10: SW101.8@3608.9,4164.41 3609,4164.5 R115.1
NetR116_1: R116.1 SW101.10 | length 99.7
  Top Layer w10: SW101.10@3658.9,4164.41 3658.9,4263.95 R116.1
NetR117_1: R117.1 SW101.12 | length 103
  Top Layer w10: SW101.12@3709,4161.03 R117.1
NetR118_1: R118.1 SW101.14 | length 99.7
  Top Layer w10: SW101.14@3758.9,4164.41 3759,4164.5 R118.1
NetR119_1: R119.1 SW102.2 | length 72.4
  Top Layer w10: SW102.2 R119.1@3086,2831.02
NetR120_1: R120.1 SW102.4 | length 72.4
  Top Layer w10: SW102.4 R120.1@3136,2831.02
NetR121_1: R121.1 SW102.6 | length 72.4
  Top Layer w10: SW102.6 R121.1@3186,2831.02
NetR122_1: R122.1 SW102.8 | length 72.4
  Top Layer w10: SW102.8 R122.1@3236,2831.02
NetR123_1: R123.1 SW102.10 | length 72.4
  Top Layer w10: SW102.10 R123.1@3286,2831.02
NetR124_1: R124.1 SW102.12 | length 72.4
  Top Layer w10: SW102.12 R124.1@3336,2831.02
NetR135_1: R135.1 U102.15 | length 97.9
  Top Layer w10: U102.15 R135.1
OE: SW101.1 U101.56 | length 568
  Top Layer w10: SW101.1@3458.94,3874.68 3458.94,3518.06 3572,3405 3572,3353.59 U101.56
ROUT_SEL: SW102.3 U101.17 | length 975.4
  Top Layer w10: SW102.3@3137,2466.75 3137,2599 3157,2619 3497,2619 3601,2723 3601,2994 3611.42,3004.42 U101.17
SCL: J101.15 JP107.1 JP108.2 | length 2860.6
  Top Layer w10: J101.15 2168.43,3001.57 2447,2723 2447,2245 2605,2087 JP107.1 2716,2026 2742,2000 2861,2000 2908,2047 2908,2246 2978,2316 v1(3018,2316)
  Bottom Layer w10: v1(3018,2316) 3200,2316 3235,2351 3862,2351 3916,2405 JP108.2
SCL_1: J102.15 R104.1 U102.5 | length 5152.9
  Top Layer w10: v1(2961,1900) 2962,1899 2962,1871 2994.73,1838.27 4665.73,1840.73 5491,2666 5491,3697 5219,3969 5089.74,3969 J102.15 5021.05,3900.05 4898,3777 R104.1 ; v1(2962,1976) 2962,2155 2971.2,2164.2 U102.5
  Bottom Layer w10: v1@2962,1901 v1(2962,1976)
SCL_2: J103.15 R107.1 U102.6 | length 2716.7
  Top Layer w10: U102.6 3090.39,2138.61 3104,2125 3104,1976 3196,1884 4655,1884 4960,2189 4960,2294.26 J103.15 4885.05,2368.95 4830,2424 4675.22,2424 R107.1
SCL_EEPROM: JP108.1 R133.1 U103.6 | length 480.7
  Top Layer w10: R133.1 3649.92,2175 3799,2175 4016,2392 JP108.1 ; U103.6 U103.6@3739.75,2175
SCL_SW: JP107.2 U102.7 | length 230.6
  Top Layer w10: v1(2987.02,2113.02) U102.7
  Bottom Layer w10: JP107.2 2842,2113 v1(2987.02,2113.02)
SDA: J101.16 JP106.1 JP109.2 | length 2264
  Top Layer w10: v1(2228,2982) 2228,2979 2479,2728 2479,2336 2606,2209 JP106.1 2712,2211 2712,2284 2803,2375 3608,2375 JP109.2
  Bottom Layer w10: J101.16 2133.89,2981.89 2143,2991 2219,2991 v1(2228,2982)
SDA_1: J102.16 R105.1 U102.2 | length 5076.8
  Top Layer w10: U102.2 2972.98,2240.98 2934,2202 2934,1965 3039,1860 3040,1860 3041,1859 4657,1859 5469,2671 5469,3669 5193,3945 5093.58,3945 J102.16 5034.97,3885.97 4946.97,3797.97 R105.1
SDA_2: J103.16 R108.1 U102.3 | length 2646.4
  Top Layer w10: U102.3 3104.61,2215.39 3141,2179 3141,2050 3270,1921 4661,1921 4934,2194 4934,2292.42 J103.16 4870.97,2355.03 4833,2393 4730,2393 4687,2350 R108.1
SDA_EEPROM: JP109.1 R134.1 U103.5 | length 326
  Top Layer w10: R134.1 3648.95,2315.95 JP109.1 ; R134.1 U103.5
SDA_SW: JP106.2 U102.4 | length 229.8
  Top Layer w10: v1@2983,2190 v1(2983.2,2189.8) U102.4
  Bottom Layer w10: JP106.2 2833,2190 v1@2983,2190
SEL1: R110.2 SW101.3 U101.55 U102.1 | length 2082
  Top Layer w10: U102.1 3110.57,2266.57 3150,2306 3150,2342 v1(3149,2343) ; v1(3508.94,3946.94) 3508.94,3509.06 3591.73,3426.27 v1@3591.73,3330.73
  Bottom Layer w10: v1(3149,2343) 3149,2492 3473,2816 3473,3312 3491.27,3330.27 v1@3591.73,3330.27 ; v1(3508.94,3946.94) R110.2@3508.94,3981.03
  other v1: 3592.73,3330.73
SEL_OUT: JP103.2 U101.16 | length 1010.2
  Top Layer w10: JP103.2 3007,2670 3007,2914 3053,2960 3540,2960 3592,3012 3592,3046.19 U101.16
SW1/I2C_ADR0: SW101.13 U101.49 | length 541.5
  Top Layer w10: U101.49 3709.84,3596.84 3758.94,3645.94 SW101.13@3758.94,3874.68
SW2/I2C_ADR1: SW101.11 U101.50 | length 529
  Top Layer w10: U101.50 3690,3353.7 3690,3621 3708.94,3639.94 SW101.11@3708.94,3874.68
WP: R131.1 R132.2 U103.7 | length 140
  Top Layer w10: R132.2 3648.98,2074.25 R131.1 U103.7
pads on no net: J101.14 J102.14 J103.14 J104.2 J104.3 J104.4 J104.10 J104.11 SW101.15 SW101.16 SW102.13 SW102.14 SW102.15 SW102.16

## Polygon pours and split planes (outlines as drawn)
+5V_USB on Top Layer "Bottom Layer-No Net" (solid, pour order 14): 2804,4290 2804,4113 2801,4113 2801,4060 2802,4059 2959,4059 2959,4128 2958,4129 2957,4128 2861,4128 2861,4290 2804,4290
+5V on Top Layer "Bottom Layer-No Net" (solid, pour order 17): 2899,3997 2900,3996 3322,3996 3322,3847 2899,3847 2899,3997
+3V3 on MidLayer1 "Bottom Layer-No Net" (solid, pour order 13): 3424,4582 3424,3498 3424,3430 3337,3343 3004,3010 3004,2682 4110,2682 4317,2889 4317,4581 3425,4581 3424,4582
+5V on MidLayer1 "Bottom Layer-No Net" (solid, pour order 12): 2562,4589 3369,4589 3369,3471 2933,3035 2930,3032 2930,2633 4161,2633 4379,2851 4385,2857 4385,4589 4959,4589 4961,4591 5601,3951 5601,3948 5601,2450 5598,2447 4936,1785 4936,1784 2537,1784 2408,1913 2406,1913 2406,2524 2306,2624 2306,2626 1976,2626 1975,2627 1907,2695 1907,2816 2004,2816 2004,3382 1908,3382 1907,3383 1907,3494 1909,3494 1981,3566 2295,3566 2297,3566 2409,3678 2409,4453 2411,4453 2547,4589 2562,4589
GND on MidLayer2 "Bottom Layer-No Net" (solid, pour order 16): 2557,4600 4953,4600 4955,4598 5603,3950 5603,3946 5603,2451 5601,2449 4936,1784 4935,1784 2534,1784 2406,1912 2406,1916 2406,2522 2405,2523 2306,2622 2306,2623 1976,2623 1973,2626 1904,2695 1904,2700 1904,2817 1906,2819 1909,2816 2003,2816 2003,3379 2004,3380 2001,3383 1909,3383 1909,3489 1907,3491 1978,3562 1978,3565 2294,3565 2296,3563 2409,3676 2409,3681 2409,4454 2555,4600 2557,4600
+3V3 on Bottom Layer "Bottom Layer-No Net" (solid, pour order 11): 3925,4507 3926,4508 4231,4508 4231,4200 4228,4203 3926,4203 3926,4506 3925,4507
GND on Bottom Layer "Bottom Layer-No Net" (solid, pour order 15): 4257,4507 4257,4202 4552,4202 4555,4199 4555,4507 4257,4507
NetD101_CATHODE on Bottom Layer "Bottom Layer-No Net" (solid, pour order 18): 2564,2870 2758,2871 2758,2764 2563,2764 2564,2870
+5V on Bottom Layer "Bottom Layer-No Net" (solid, pour order 19): 2788,2869 2789,2774 2921,2774 2920,2869 2788,2869
+5V_S on Bottom Layer "Bottom Layer-No Net" (solid, pour order 20): 2128,2953 2610,2953 2610,2914 2128,2918 2128,2953

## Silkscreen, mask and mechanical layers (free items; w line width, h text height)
Top Overlay:
  lines w5: 3119,2351 3119,2409 3135,2425 ; 3187,2392 3183,2388 3183,2370 3199,2354 3199,2347 ; 3309,2399 3315,2405 3359,2405
  text "GND" at 4466,4105 h60
  text "+3.3V" at 3906,4092 h60
  text "OE" at 3427,3811 h50 r270
  text "SEL1" at 3491,3811 h50 r270
  text "DR" at 3544,3811 h50 r270
  text "SW1/I2C_ADR0" at 3744,3810 h50 r270
  text "EMP2/I2C-ADR3" at 3595,3809 h50 r270
  text "EMP1/I2C_ADR2" at 3643,3808 h50 r270
  text "SW2/ADR1" at 3695,3806 h50 r270
  text "MS" at 3020,2498 h60 r270
  text "EQ1/SDA" at 3364,2392 h60
  text "EQ2/SCL" at 3206,2334 h60
  text "ROUT_SEL" at 2849,2330 h60
Bottom Overlay:
  rectangle: 2610,3332.5 3240,3512.5
  text "PI3HDMI412BDZBE_HDMI SW_EVB" at 3373,3607 h60
  text "Date:2013.12.3" at 3369,3537 h60
  text "REV.B" at 2964,3536 h60
  text "S/N:" at 3357,3415 h60
  text "1409DB268" at 4816,1811 h60
Mechanical 1:
  the board outline again, w5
